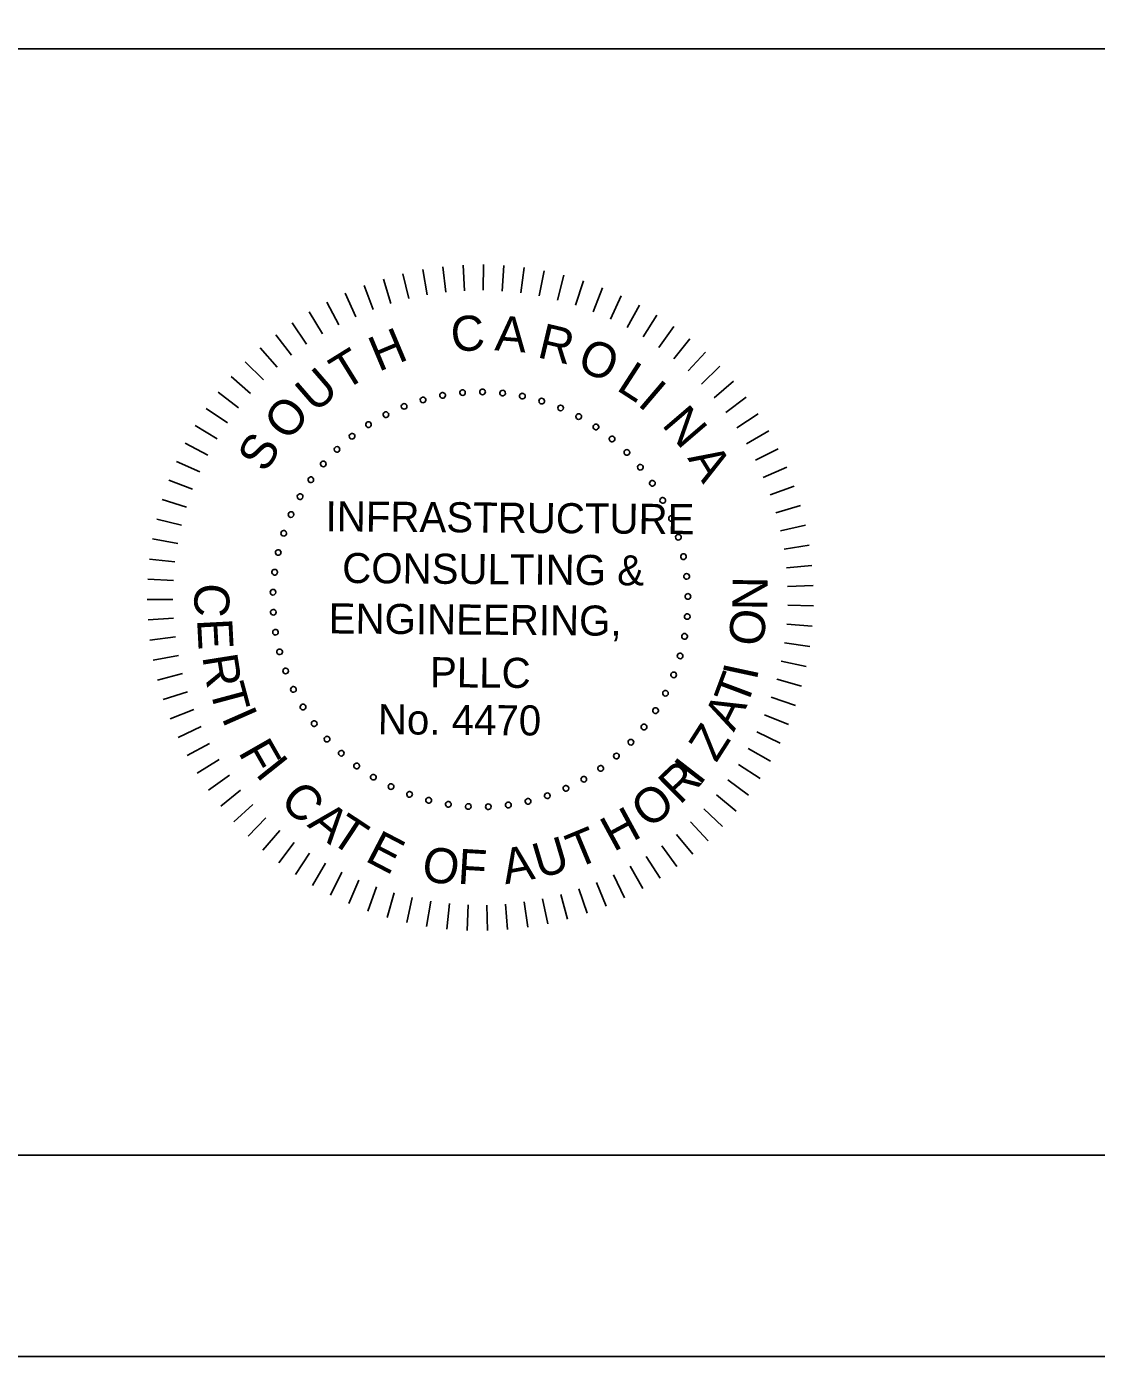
# Model space of a CAD drawing. Extents: x -55.6 to -19.5, y -5.1 to 16.9.
# Drawn here: x -30.378 to -27.72, y -5.092 to -1.787 of the extents above; entities that cross this region are included whole.
import ezdxf

# ---------------------------------------------------------------- set-up
doc = ezdxf.new("R2010")
doc.units = 0
for name, color, linetype in [('BR_BORDER LINES', 7, 'Continuous'), ('BR_TEXT', 7, 'Continuous'), ('Level 31', 7, 'Continuous')]:
    doc.layers.add(name, color=color, linetype=linetype)

msp = doc.modelspace()

# ---------------------------------------------------------------- linework, layer by layer
at = {"layer": 'BR_BORDER LINES'}
for p, q in [((-32.9495, -1.8415), (-27.5843, -1.8415)), ((-53.7501, -4.5917), (-20.084, -4.5917))]:
    msp.add_line(p, q, dxfattribs=at)
at = {"layer": 'BR_TEXT'}
for p, q in [((-29.2934, -2.3793), (-29.29, -2.4429)), ((-29.2429, -2.3782), (-29.2434, -2.4419)), ((-29.4431, -2.4008), (-29.4282, -2.4627)), ((-29.3936, -2.3906), (-29.3826, -2.4533)), ((-29.3437, -2.3834), (-29.3365, -2.4467)), ((-29.1924, -2.3802), (-29.1969, -2.4438)), ((-29.1422, -2.3853), (-29.1505, -2.4485)), ((-29.0924, -2.3935), (-29.1045, -2.456)), ((-29.0432, -2.4046), (-29.0591, -2.4663)), ((-29.5396, -2.4302), (-29.5173, -2.4899)), ((-29.4918, -2.4141), (-29.4732, -2.475)), ((-28.9947, -2.4188), (-29.0143, -2.4793)), ((-28.9472, -2.4358), (-28.9705, -2.4951)), ((-29.6319, -2.4712), (-29.6025, -2.5276)), ((-29.5864, -2.4493), (-29.5605, -2.5075)), ((-28.9008, -2.4558), (-28.9277, -2.5135)), ((-28.8557, -2.4785), (-28.8861, -2.5345)), ((-29.676, -2.4958), (-29.6432, -2.5503)), ((-28.8121, -2.5039), (-28.8458, -2.558)), ((-29.7185, -2.523), (-29.6824, -2.5755)), ((-28.7701, -2.532), (-28.8071, -2.5839)), ((-29.7592, -2.5528), (-29.72, -2.603)), ((-28.73, -2.5625), (-28.77, -2.6121)), ((-29.7981, -2.585), (-29.7559, -2.6327)), ((-28.6917, -2.5955), (-28.7347, -2.6425)), ((-29.8349, -2.6195), (-29.7899, -2.6646)), ((-28.6555, -2.6307), (-28.7013, -2.675)), ((-29.8696, -2.6562), (-29.8219, -2.6985)), ((-28.6216, -2.6681), (-28.6699, -2.7095)), ((-29.9019, -2.695), (-29.8518, -2.7342)), ((-28.59, -2.7074), (-28.6407, -2.7458)), ((-29.9319, -2.7356), (-29.8794, -2.7717)), ((-28.5608, -2.7486), (-28.6138, -2.7839)), ((-29.9593, -2.778), (-29.9047, -2.8109)), ((-28.5342, -2.7915), (-28.5893, -2.8235)), ((-29.984, -2.822), (-29.9276, -2.8515)), ((-28.5103, -2.836), (-28.5672, -2.8645)), ((-30.0061, -2.8674), (-29.948, -2.8934)), ((-28.4891, -2.8818), (-28.5477, -2.9068)), ((-30.0253, -2.9141), (-29.9657, -2.9365)), ((-28.4708, -2.9289), (-28.5307, -2.9502)), ((-30.0417, -2.9619), (-29.9808, -2.9806)), ((-28.4553, -2.9769), (-28.5165, -2.9946)), ((-30.0551, -3.0106), (-29.9932, -3.0255)), ((-28.4428, -3.0258), (-28.505, -3.0398)), ((-30.0655, -3.06), (-30.0028, -3.0711)), ((-28.4334, -3.0754), (-28.4962, -3.0855)), ((-30.0729, -3.1099), (-30.0096, -3.1172)), ((-28.4269, -3.1255), (-28.4903, -3.1318)), ((-30.0772, -3.1602), (-30.0136, -3.1636)), ((-28.4236, -3.1759), (-28.4872, -3.1783)), ((-30.0784, -3.2107), (-30.0148, -3.2102)), ((-28.4233, -3.2264), (-28.4869, -3.2249)), ((-30.0766, -3.2611), (-30.0131, -3.2568)), ((-28.4261, -3.2768), (-28.4895, -3.2714)), ((-30.0717, -3.3114), (-30.0086, -3.3032)), ((-28.4319, -3.3269), (-28.4949, -3.3177)), ((-30.0637, -3.3612), (-30.0012, -3.3492)), ((-28.4408, -3.3766), (-28.5031, -3.3635)), ((-30.0528, -3.4105), (-29.9911, -3.3947)), ((-28.4527, -3.4257), (-28.5141, -3.4088)), ((-30.0388, -3.459), (-29.9782, -3.4395)), ((-28.4676, -3.4739), (-28.5279, -3.4534)), ((-30.0219, -3.5066), (-29.9626, -3.4834)), ((-28.4854, -3.5211), (-28.5443, -3.497)), ((-30.0021, -3.553), (-29.9444, -3.5263)), ((-29.9796, -3.5982), (-29.9235, -3.5679)), ((-28.5061, -3.5672), (-28.5634, -3.5395)), ((-28.5295, -3.6119), (-28.585, -3.5808)), ((-29.9543, -3.6419), (-29.9002, -3.6083)), ((-28.5556, -3.6552), (-28.6091, -3.6207)), ((-29.9264, -3.684), (-29.8745, -3.6471)), ((-28.5842, -3.6967), (-28.6356, -3.659)), ((-29.896, -3.7243), (-29.8464, -3.6843)), ((-28.6154, -3.7364), (-28.6643, -3.6957)), ((-29.8632, -3.7627), (-29.8161, -3.7198)), ((-28.6489, -3.7742), (-28.6953, -3.7305)), ((-29.8281, -3.799), (-29.7838, -3.7533)), ((-28.6847, -3.8098), (-28.7283, -3.7634)), ((-29.7909, -3.833), (-29.7494, -3.7848)), ((-28.7226, -3.8432), (-28.7633, -3.7942)), ((-29.7517, -3.8648), (-29.7132, -3.8141)), ((-28.7624, -3.8742), (-28.8, -3.8228)), ((-29.7105, -3.8941), (-29.6752, -3.8411)), ((-29.6677, -3.9209), (-29.6357, -3.8658)), ((-28.8041, -3.9027), (-28.8385, -3.8492)), ((-29.6234, -3.945), (-29.5948, -3.8881)), ((-28.8922, -3.9519), (-28.9198, -3.8945)), ((-28.8474, -3.9287), (-28.8785, -3.8731)), ((-29.5776, -3.9663), (-29.5525, -3.9078)), ((-29.5307, -3.9848), (-29.5092, -3.9249)), ((-28.9856, -3.99), (-29.0061, -3.9297)), ((-28.9383, -3.9724), (-28.9624, -3.9134)), ((-29.4826, -4.0004), (-29.4649, -3.9393)), ((-29.4338, -4.0131), (-29.4198, -3.951)), ((-29.3842, -4.0228), (-29.374, -3.9599)), ((-29.3342, -4.0294), (-29.3278, -3.966)), ((-29.1328, -4.0251), (-29.1419, -3.9621)), ((-29.083, -4.0164), (-29.096, -3.9541)), ((-29.0339, -4.0047), (-29.0507, -3.9433)), ((-29.2838, -4.0329), (-29.2814, -3.9693)), ((-29.2333, -4.0334), (-29.2348, -3.9698)), ((-29.1829, -4.0308), (-29.1882, -3.9674))]:
    msp.add_line(p, q, dxfattribs=at)
for centre, start, end in [((-29.393, -2.7144), 16.1422, 196.1422), ((-29.3445, -2.703), 10.6038, 190.6038), ((-29.3445, -2.703), 190.6038, 10.6038), ((-29.2951, -2.6963), 5.0653, 185.0653), ((-29.2951, -2.6963), 185.0653, 5.0653), ((-29.2453, -2.6944), 359.5268, 179.5268), ((-29.2453, -2.6944), 179.5268, 359.5268), ((-29.1956, -2.6973), 173.9884, 353.9884), ((-29.1956, -2.6973), 353.9884, 173.9884), ((-29.1463, -2.705), 168.4499, 348.4499), ((-29.1463, -2.705), 348.4499, 168.4499), ((-29.4402, -2.7304), 21.6807, 201.6807), ((-29.4402, -2.7304), 201.6807, 21.6807), ((-29.393, -2.7144), 196.1422, 16.1422), ((-29.0981, -2.7174), 162.9114, 342.9114), ((-29.0981, -2.7174), 342.9114, 162.9114), ((-29.0513, -2.7344), 157.373, 337.373), ((-29.0513, -2.7344), 337.373, 157.373), ((-29.5288, -2.7758), 32.7576, 212.7576), ((-29.5288, -2.7758), 212.7576, 32.7576), ((-29.4856, -2.751), 27.2191, 207.2191), ((-29.4856, -2.751), 207.2191, 27.2191), ((-29.0063, -2.7559), 151.8345, 331.8345), ((-29.0063, -2.7559), 331.8345, 151.8345), ((-28.9636, -2.7816), 326.2961, 146.2961), ((-29.5694, -2.8047), 38.2961, 218.2961), ((-29.5694, -2.8047), 218.2961, 38.2961), ((-28.9636, -2.7816), 146.2961, 326.2961), ((-28.9236, -2.8113), 140.7576, 320.7576), ((-28.9236, -2.8113), 320.7576, 140.7576), ((-29.607, -2.8373), 43.8345, 223.8345), ((-29.607, -2.8373), 223.8345, 43.8345), ((-28.8866, -2.8447), 135.2191, 315.2191), ((-28.8866, -2.8447), 315.2191, 135.2191), ((-29.6413, -2.8735), 49.373, 229.373), ((-29.6413, -2.8735), 229.373, 49.373), ((-28.8531, -2.8816), 309.6807, 129.6807), ((-29.672, -2.9128), 54.9114, 234.9114), ((-29.672, -2.9128), 234.9114, 54.9114), ((-28.8531, -2.8816), 129.6807, 309.6807), ((-28.8232, -2.9215), 124.1422, 304.1422), ((-28.8232, -2.9215), 304.1422, 124.1422), ((-29.6987, -2.9548), 60.4499, 240.4499), ((-29.6987, -2.9548), 240.4499, 60.4499), ((-28.7974, -2.9641), 118.6038, 298.6038), ((-28.7974, -2.9641), 298.6038, 118.6038), ((-29.7213, -2.9993), 65.9884, 245.9884), ((-29.7213, -2.9993), 245.9884, 65.9884), ((-28.7757, -3.0089), 113.0653, 293.0653), ((-28.7757, -3.0089), 293.0653, 113.0653), ((-29.7394, -3.0457), 71.5268, 251.5268), ((-29.7394, -3.0457), 251.5268, 71.5268), ((-28.7585, -3.0557), 107.5268, 287.5268), ((-28.7585, -3.0557), 287.5268, 107.5268), ((-29.753, -3.0936), 77.0653, 257.0653), ((-29.753, -3.0936), 257.0653, 77.0653), ((-28.7459, -3.1039), 101.9884, 281.9884), ((-28.7459, -3.1039), 281.9884, 101.9884), ((-29.7619, -3.1426), 82.6038, 262.6038), ((-29.7619, -3.1426), 262.6038, 82.6038), ((-28.7381, -3.1531), 96.4499, 276.4499), ((-28.7381, -3.1531), 276.4499, 96.4499), ((-29.766, -3.1923), 88.1422, 268.1422), ((-29.766, -3.1923), 268.1422, 88.1422), ((-28.735, -3.2029), 90.9114, 270.9114), ((-28.735, -3.2029), 270.9114, 90.9114), ((-29.7653, -3.2421), 93.6807, 273.6807), ((-29.7653, -3.2421), 273.6807, 93.6807), ((-28.7367, -3.2527), 85.373, 265.373), ((-28.7367, -3.2527), 265.373, 85.373), ((-29.7598, -3.2917), 99.2191, 279.2191), ((-29.7598, -3.2917), 279.2191, 99.2191), ((-28.7432, -3.3021), 79.8345, 259.8345), ((-28.7432, -3.3021), 259.8345, 79.8345), ((-29.7496, -3.3404), 104.7576, 284.7576), ((-29.7496, -3.3404), 284.7576, 104.7576), ((-28.7544, -3.3506), 74.2961, 254.2961), ((-28.7544, -3.3506), 254.2961, 74.2961), ((-29.7346, -3.388), 110.2961, 290.2961), ((-29.7346, -3.388), 290.2961, 110.2961), ((-28.7703, -3.3978), 68.7576, 248.7576), ((-28.7703, -3.3978), 248.7576, 68.7576), ((-29.7152, -3.4339), 115.8345, 295.8345), ((-29.7152, -3.4339), 295.8345, 115.8345), ((-28.7907, -3.4433), 63.2191, 243.2191), ((-28.7907, -3.4433), 243.2191, 63.2191), ((-29.6914, -3.4777), 121.373, 301.373), ((-29.6914, -3.4777), 301.373, 121.373), ((-28.8153, -3.4866), 57.6807, 237.6807), ((-28.8153, -3.4866), 237.6807, 57.6807), ((-29.6636, -3.5189), 126.9114, 306.9114), ((-29.6636, -3.5189), 306.9114, 126.9114), ((-28.8441, -3.5273), 52.1422, 232.1422), ((-28.8441, -3.5273), 232.1422, 52.1422), ((-29.6318, -3.5574), 132.4499, 312.4499), ((-29.6318, -3.5574), 312.4499, 132.4499), ((-28.8766, -3.5651), 46.6038, 226.6038), ((-28.8766, -3.5651), 226.6038, 46.6038), ((-29.5965, -3.5925), 137.9884, 317.9884), ((-29.5965, -3.5925), 317.9884, 137.9884), ((-28.9126, -3.5995), 41.0653, 221.0653), ((-28.9126, -3.5995), 221.0653, 41.0653), ((-29.558, -3.6241), 143.5268, 323.5268), ((-29.558, -3.6241), 323.5268, 143.5268), ((-28.9518, -3.6303), 35.5268, 215.5268), ((-28.9518, -3.6303), 215.5268, 35.5268), ((-29.5166, -3.6519), 149.0653, 329.0653), ((-29.5166, -3.6519), 329.0653, 149.0653), ((-29.4727, -3.6755), 334.6038, 154.6038), ((-28.9937, -3.6572), 29.9884, 209.9884), ((-28.9937, -3.6572), 209.9884, 29.9884), ((-29.4727, -3.6755), 154.6038, 334.6038), ((-29.4267, -3.6947), 160.1422, 340.1422), ((-29.4267, -3.6947), 340.1422, 160.1422), ((-29.0844, -3.6982), 18.9114, 198.9114), ((-29.0844, -3.6982), 198.9114, 18.9114), ((-29.0381, -3.6799), 24.4499, 204.4499), ((-29.0381, -3.6799), 204.4499, 24.4499), ((-29.3791, -3.7095), 165.6807, 345.6807), ((-29.3791, -3.7095), 345.6807, 165.6807), ((-29.3303, -3.7195), 351.2191, 171.2191), ((-29.3303, -3.7195), 171.2191, 351.2191), ((-29.2808, -3.7249), 356.7576, 176.7576), ((-29.2808, -3.7249), 176.7576, 356.7576), ((-29.231, -3.7254), 2.2961, 182.2961), ((-29.231, -3.7254), 182.2961, 2.2961), ((-29.1813, -3.7211), 7.8345, 187.8345), ((-29.1813, -3.7211), 187.8345, 7.8345), ((-29.1323, -3.712), 13.373, 193.373), ((-29.1323, -3.712), 193.373, 13.373)]:
    msp.add_arc(centre, 0.00701, start, end, dxfattribs=at)
at = {"layer": 'Level 31'}
msp.add_lwpolyline([(-55.5834, -5.0916), (-19.5834, -5.0916), (-19.5834, 16.9084), (-55.5834, 16.9084)], close=True, dxfattribs=at)

# ---------------------------------------------------------------- texts
at = {"layer": 'BR_TEXT'}
for s, height, rotation, p in [('C', 0.0872, 4.7281, (-29.3208, -2.5958)), ('A', 0.0872, 355.6981, (-29.2164, -2.5909)), ('H', 0.0872, 22.7882, (-29.5037, -2.6452)), ('R', 0.0872, 346.6681, (-29.1121, -2.6078)), ('O', 0.0872, 337.638, (-29.0143, -2.6377)), ('T', 0.0872, 31.8182, (-29.5885, -2.6929)), ('U', 0.0872, 40.8482, (-29.6618, -2.749)), ('L', 0.0872, 327.108, (-28.9155, -2.6881)), ('I', 0.0872, 319.578, (-28.8629, -2.7259)), ('O', 0.0872, 49.8782, (-29.7288, -2.82)), ('N', 0.0872, 310.548, (-28.8021, -2.7767)), ('S', 0.0872, 58.9083, (-29.7842, -2.8982)), ('A', 0.0872, 301.5179, (-28.7371, -2.8591)), ('INFRASTRUCTURE', 0.074771, 359.5268, (-29.6356, -3.0407)), ('CONSULTING &', 0.074771, 359.5268, (-29.5943, -3.1693)), ('N', 0.0872, 89.2085, (-28.5378, -3.2379)), ('C', 0.0872, 267.025, (-29.9592, -3.1681)), ('ENGINEERING,', 0.074771, 359.5268, (-29.6279, -3.2947)), ('O', 0.0872, 83.2085, (-28.5488, -3.3293)), ('E', 0.0872, 273.025, (-29.9548, -3.2597)), ('R', 0.0872, 279.025, (-29.942, -3.352)), ('PLLC', 0.07477, 359.5268, (-29.3762, -3.4283)), ('T', 0.0872, 69.3954, (-28.5901, -3.4811)), ('I', 0.0872, 77.9093, (-28.5644, -3.4136)), ('T', 0.0872, 285.025, (-29.9246, -3.4307)), ('A', 0.0872, 63.3954, (-28.6209, -3.5414)), ('I', 0.0872, 293.7713, (-29.8949, -3.5038)), ('No. 4470', 0.07477, 359.5268, (-29.5057, -3.5452)), ('Z', 0.0872, 57.3954, (-28.6647, -3.6178)), ('F', 0.0872, 299.7713, (-29.8538, -3.5899)), ('I', 0.0872, 308.5268, (-29.8117, -3.6438)), ('R', 0.0872, 44.5268, (-28.7551, -3.7227)), ('I', 0.0872, 52.3339, (-28.7058, -3.6755)), ('C', 0.0872, 314.5268, (-29.7523, -3.7139)), ('O', 0.0872, 38.5268, (-28.8317, -3.7827)), ('A', 0.0872, 320.5268, (-29.6832, -3.7725)), ('H', 0.0872, 28.5268, (-28.9198, -3.8387)), ('T', 0.0872, 326.5268, (-29.6287, -3.8109)), ('E', 0.0872, 332.5268, (-29.5401, -3.8587)), ('U', 0.0872, 16.5268, (-29.1047, -3.9049)), ('T', 0.0872, 22.5268, (-29.013, -3.8805)), ('O', 0.0872, 350.5268, (-29.4, -3.9076)), ('F', 0.0872, 356.5268, (-29.3085, -3.9167)), ('A', 0.0872, 10.5268, (-29.1887, -3.9184))]:
    msp.add_text(s, height=height, rotation=rotation, dxfattribs=at).set_placement(p)

doc.saveas('drawing.dxf')
